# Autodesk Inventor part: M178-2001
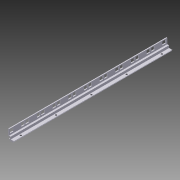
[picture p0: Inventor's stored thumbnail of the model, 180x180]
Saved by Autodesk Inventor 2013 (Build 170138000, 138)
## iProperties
Created: 2004-11
Material: Aluminium - 6061
Document SubType Name: Modeling
Designer: Autodesk, Inc.
Manufacturer: Standard
Standards Organization: Custom
Description: PC RACK, MOUNT ANGLE, 4U
Stock Number: 12-109M
Catalog Web Link: http://www.parker.com/ead/cm1.asp?cmid=809
Vendor: PARKER IPS
Part Number: M178-2001
Mass: 126.265 g
Surface Area: 389.073 cm^2
Volume: 46.5923 cm^3
Density: 2.71 g/cm^3
CAGE: 1LJX3
Dept. ID: Product Design
Description #2: ---
Finish #1: ---
Finish #2: ---
Material ID: ---
Project Number: ---
Author: Autodesk, Inc.
Revision Number: A
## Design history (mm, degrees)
derived "Rack Angle (19in).ipt"
body "Solid1"
tag "TaggingFeature2"
feature "Solid1::Rack Angle (19in).ipt" dims "ScaleForDerivedMember" = 10
other parameters: "Length" = 182.05
